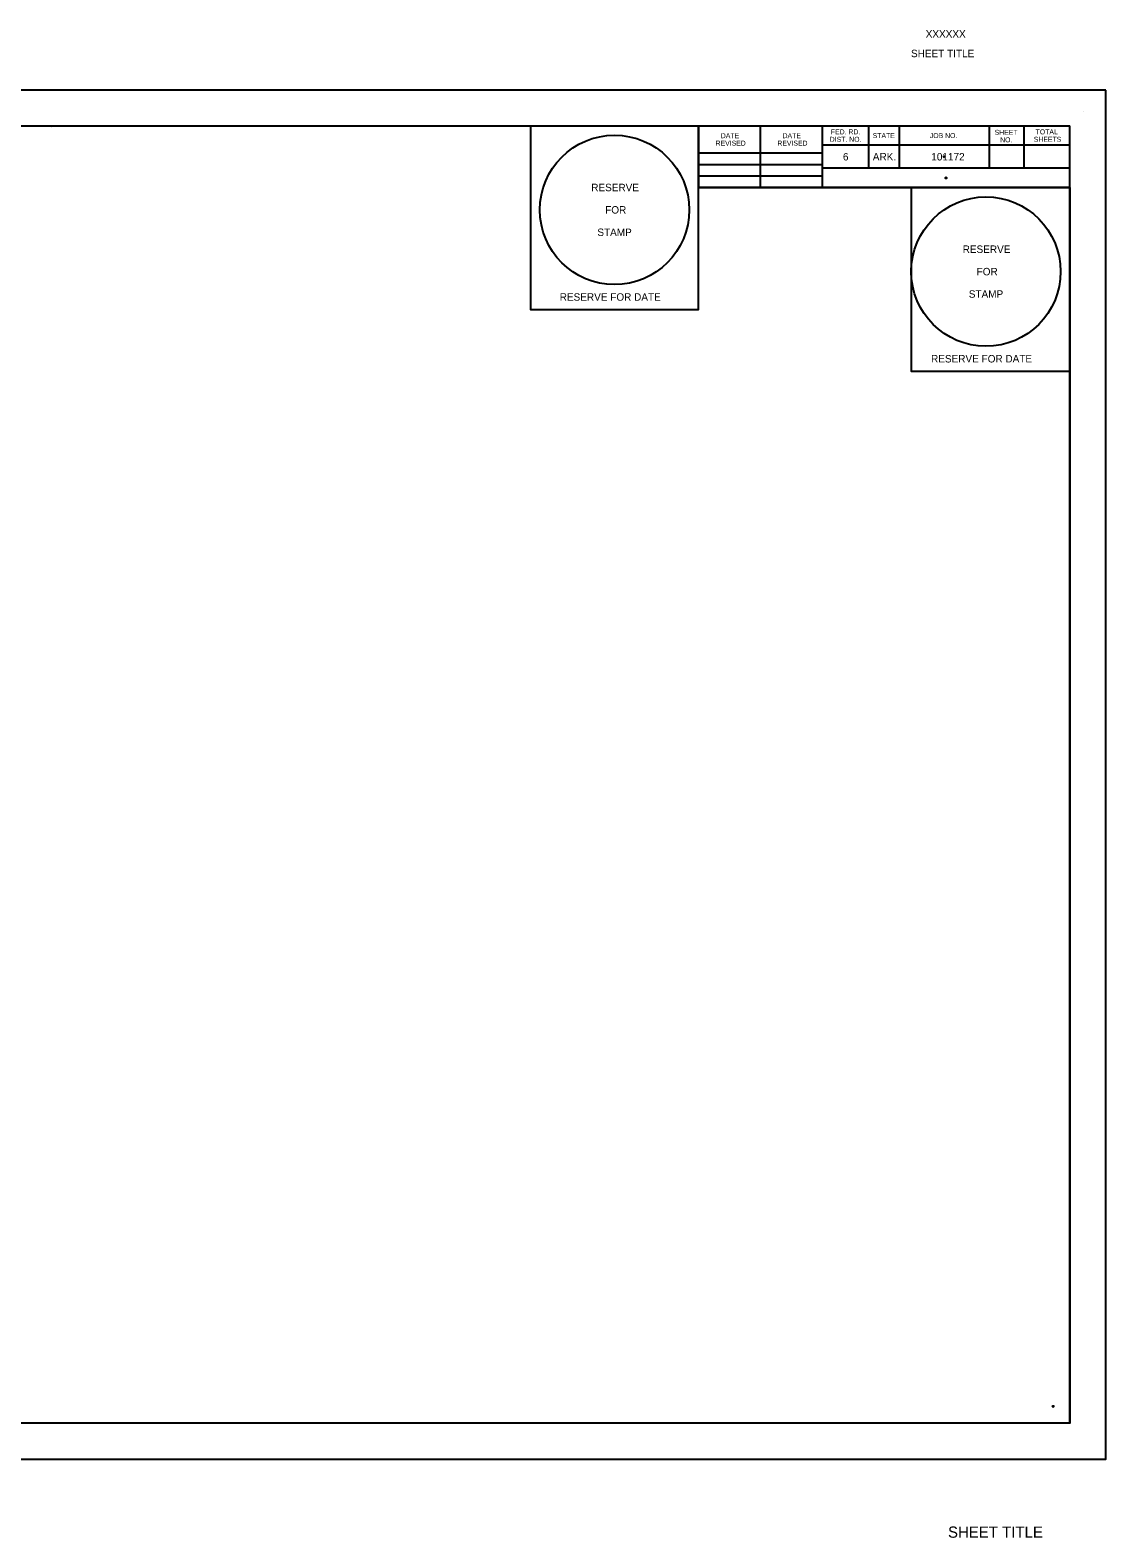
# Model space of a CAD drawing. Extents: x 0 to 17, y -0.6 to 11.5.
# Drawn here: x 8.36 to 17, y -0.63 to 11.48 of the extents above; entities that cross this region are included whole.
import ezdxf

# ---------------------------------------------------------------- set-up
doc = ezdxf.new("R2010")
doc.units = 0
for name, color, linetype in [('G-ANNO-TEXT', 7, 'Continuous'), ('G-Border-Paper', 7, 'Continuous'), ('G-Border-Sheet', 7, 'Continuous'), ('G-No Plot-Anchor', 7, 'Continuous'), ('G-No Plot-Border-1', 7, 'Continuous'), ('G-No Plot-Border-2', 7, 'Continuous'), ('G-No Plot-Stamp-1', 7, 'Continuous'), ('G-No Plot-Stamp-2', 7, 'Continuous'), ('G-Table-Major', 7, 'Continuous'), ('G-Table-Minor', 7, 'Continuous')]:
    doc.layers.add(name, color=color, linetype=linetype)

msp = doc.modelspace()

# ---------------------------------------------------------------- linework, layer by layer
at = {"layer": 'G-ANNO-TEXT'}
msp.add_line((16.821, 10.827), (16.821, 10.827), dxfattribs=at)
at = {"layer": 'G-Border-Paper'}
msp.add_lwpolyline([(17, 11), (0, 11), (0, 0), (17, 0)], close=True, dxfattribs=at)
at = {"layer": 'G-Border-Sheet'}
for p, q in [((0.758, 10.712), (16.712, 10.712)), ((16.712, 0.288), (16.712, 10.712)), ((16.712, 0.288), (0.758, 0.288))]:
    msp.add_line(p, q, dxfattribs=at)
at = {"layer": 'G-No Plot-Anchor'}
for centre in [(15.701, 10.464), (15.716, 10.294), (16.577, 0.423)]:
    msp.add_circle(centre, 0.005, dxfattribs=at)
at = {"layer": 'G-No Plot-Border-1'}
msp.add_lwpolyline([(0.758, 0.288), (0.758, 10.712), (13.728, 10.712), (13.728, 10.216), (15.437, 10.216), (15.437, 8.741), (16.712, 8.741), (16.712, 0.288)], close=True, dxfattribs=at)
at = {"layer": 'G-No Plot-Border-2'}
msp.add_lwpolyline([(0.758, 0.288), (0.758, 10.712), (12.378, 10.712), (12.378, 9.237), (13.728, 9.237), (13.728, 10.216), (14.721, 10.216), (16.712, 10.216), (16.712, 0.288)], close=True, dxfattribs=at)
at = {"layer": 'G-No Plot-Stamp-1'}
msp.add_circle((16.037, 9.541), 0.6, dxfattribs=at)
at = {"layer": 'G-No Plot-Stamp-2'}
msp.add_circle((13.053, 10.037), 0.6, dxfattribs=at)
at = {"layer": 'G-Table-Major'}
for p, q in [((13.728, 10.217), (13.728, 10.712)), ((14.721, 10.712), (14.721, 10.216)), ((13.728, 10.495), (14.721, 10.495)), ((16.712, 10.216), (13.728, 10.216))]:
    msp.add_line(p, q, dxfattribs=at)
at = {"layer": 'G-Table-Minor'}
for p, q in [((8.529, 10.699), (8.529, 10.699)), ((8.529, 10.699), (8.529, 10.699)), ((14.226, 10.216), (14.226, 10.712)), ((15.093, 10.712), (15.093, 10.372)), ((15.341, 10.712), (15.341, 10.372)), ((16.062, 10.712), (16.062, 10.372)), ((16.34, 10.712), (16.34, 10.372)), ((16.712, 10.556), (14.721, 10.556)), ((16.712, 10.566), (16.712, 10.566)), ((13.728, 10.401), (14.721, 10.401)), ((13.728, 10.31), (14.721, 10.31)), ((16.712, 10.372), (14.721, 10.372))]:
    msp.add_line(p, q, dxfattribs=at)

# ---------------------------------------------------------------- texts
at = {"layer": 'G-ANNO-TEXT'}
for s, height, p in [('XXXXXX', 0.06, (15.553, 11.421)), ('SHEET TITLE', 0.06, (15.435, 11.264)), ('FED. RD.', 0.04, (14.791, 10.644)), ('SHEET', 0.04, (16.107, 10.64)), ('TOTAL', 0.04, (16.436, 10.644)), ('REVISED', 0.04, (13.865, 10.553)), ('DATE', 0.04, (13.907, 10.613)), ('REVISED', 0.04, (14.361, 10.553)), ('DATE', 0.04, (14.403, 10.613)), ('DIST. NO.', 0.04, (14.782, 10.584)), ('STATE', 0.04, (15.127, 10.614)), ('JOB NO.', 0.04, (15.586, 10.614)), ('NO.', 0.04, (16.151, 10.58)), ('SHEETS', 0.04, (16.421, 10.584)), ('6', 0.06, (14.888, 10.434)), ('ARK.', 0.06, (15.128, 10.434)), ('101172', 0.06, (15.598, 10.434)), ('SHEET TITLE', 0.09, (15.732, -0.632))]:
    msp.add_text(s, height=height, dxfattribs=at).set_placement(p)
at = {"layer": 'G-No Plot-Stamp-1'}
for s, p in [('RESERVE', (15.85, 9.691)), ('FOR ', (15.962, 9.511)), ('STAMP', (15.899, 9.331)), ('RESERVE FOR DATE', (15.596, 8.811))]:
    msp.add_text(s, height=0.06, dxfattribs=at).set_placement(p)
at = {"layer": 'G-No Plot-Stamp-2'}
for s, p in [('RESERVE', (12.866, 10.187)), ('FOR ', (12.978, 10.007)), ('STAMP', (12.915, 9.827)), ('RESERVE FOR DATE', (12.613, 9.307))]:
    msp.add_text(s, height=0.06, dxfattribs=at).set_placement(p)

doc.saveas('drawing.dxf')
